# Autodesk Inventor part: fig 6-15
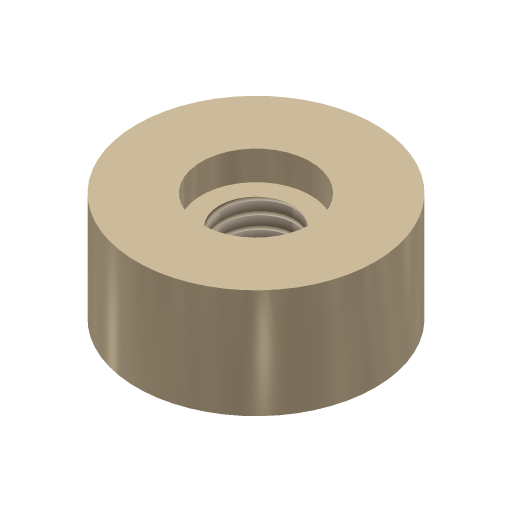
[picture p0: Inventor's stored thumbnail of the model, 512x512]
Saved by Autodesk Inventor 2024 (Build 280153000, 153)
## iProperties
Shininess: 65.0
Angle Display Precision: 2
Document Length Units: 11269
Document Angle Units: 11279
Document Time Units: 11290
Document Mass Units: 11283
Document Length Units Precision: 3
Document Angle Units Precision: 2
Created: 2001-11
Part Number: fig 6-15
Document SubType Name: Modeling
Designer: Renu Muthoo
Density: 1 g/cm^3
Material: Generic
Appearance: Metal-Titanium (Polished)
Density: 0.0
Volumn: 0.0
Area: 0.0
PropertySet Name: Model Information
Control State: 0
Master: False
Checked Out: False
Author: Renu Muthoo
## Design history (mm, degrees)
sketch "Sketch1"
  geometry: C1 r 16.401 at (0, 0)
  constraints: 1 centre point
extrude "Extrusion1" new body sketch "Sketch1" distance "d0" = 15; taper "d1" = 0 deg
hole "Hole3" diameter "d18" = 10.106; stored, may be unused: countersink angle "d22" = 90 deg, drill point angle "d24" = 118 deg; dims "d16" = 10, "d17" = 10, "d19" = 6, "d20" = 15, "d21" = 4, "d23" = 10
body "Solid1"
